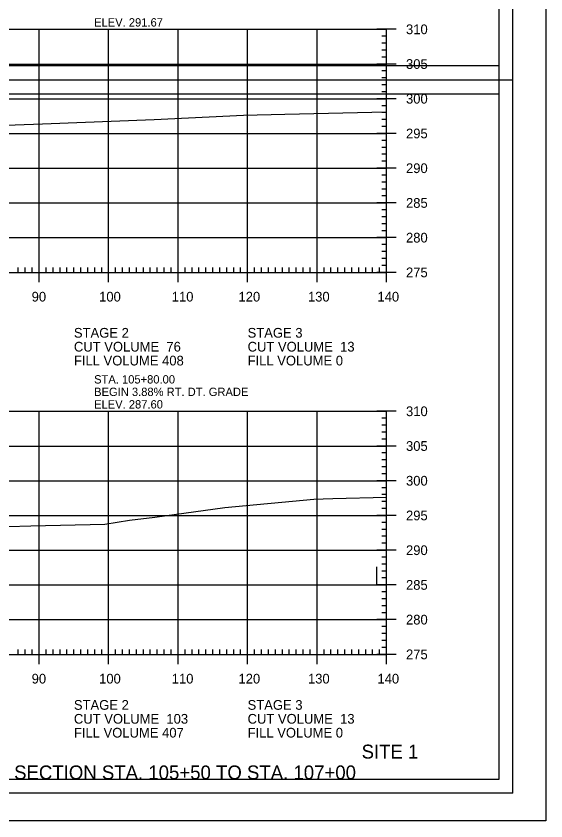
# Model space of a CAD drawing. Extents: x 1368713 to 1370673, y 380279 to 380950.
# Drawn here: x 1370239 to 1370315.2, y 380523.8 to 380639.7 of the extents above; entities that cross this region are included whole.
import ezdxf

# ---------------------------------------------------------------- set-up
doc = ezdxf.new("R2010")
doc.units = 0
for name, color, linetype in [('Notes', 7, 'Continuous'), ('R_Axis', 7, 'Continuous'), ('R_Axis Annot', 7, 'Continuous'), ('R_Border', 7, 'Continuous'), ('R_Border Plan-Plan', 7, 'Continuous'), ('R_Draft', 7, 'Continuous'), ('R_Exist Surface', 7, 'Continuous'), ('R_Grid', 7, 'Continuous'), ('R_No Plot', 7, 'Continuous'), ('R_Water', 7, 'Continuous')]:
    doc.layers.add(name, color=color, linetype=linetype)

msp = doc.modelspace()

# ---------------------------------------------------------------- linework, layer by layer
at = {"layer": 'R_Axis'}
for p, q in [((1370293.68, 380637.75), (1370290.88, 380637.75)), ((1370292.28, 380602.75), (1370292.28, 380637.75)), ((1370292.28, 380636.75), (1370291.58, 380636.75)), ((1370292.28, 380635.75), (1370291.58, 380635.75)), ((1370292.28, 380634.75), (1370291.58, 380634.75)), ((1370292.28, 380633.75), (1370291.58, 380633.75)), ((1370293.68, 380632.75), (1370290.88, 380632.75)), ((1370292.28, 380631.75), (1370291.58, 380631.75)), ((1370292.28, 380630.75), (1370291.58, 380630.75)), ((1370292.28, 380629.75), (1370291.58, 380629.75)), ((1370292.28, 380628.75), (1370291.58, 380628.75)), ((1370293.68, 380627.75), (1370290.88, 380627.75)), ((1370292.28, 380626.75), (1370291.58, 380626.75)), ((1370292.28, 380625.75), (1370291.58, 380625.75)), ((1370292.28, 380624.75), (1370291.58, 380624.75)), ((1370292.28, 380623.75), (1370291.58, 380623.75)), ((1370293.68, 380622.75), (1370290.88, 380622.75)), ((1370292.28, 380621.75), (1370291.58, 380621.75)), ((1370292.28, 380620.75), (1370291.58, 380620.75)), ((1370292.28, 380619.75), (1370291.58, 380619.75)), ((1370292.28, 380618.75), (1370291.58, 380618.75)), ((1370293.68, 380617.75), (1370290.88, 380617.75)), ((1370292.28, 380616.75), (1370291.58, 380616.75)), ((1370292.28, 380615.75), (1370291.58, 380615.75)), ((1370292.28, 380614.75), (1370291.58, 380614.75)), ((1370292.28, 380613.75), (1370291.58, 380613.75)), ((1370293.68, 380612.75), (1370290.88, 380612.75)), ((1370292.28, 380611.75), (1370291.58, 380611.75)), ((1370292.28, 380610.75), (1370291.58, 380610.75)), ((1370292.28, 380609.75), (1370291.58, 380609.75)), ((1370292.28, 380608.75), (1370291.58, 380608.75)), ((1370293.68, 380607.75), (1370290.88, 380607.75)), ((1370292.28, 380606.75), (1370291.58, 380606.75)), ((1370292.28, 380605.75), (1370291.58, 380605.75)), ((1370242.28, 380601.35), (1370242.28, 380604.15)), ((1370252.28, 380601.35), (1370252.28, 380604.15)), ((1370262.28, 380601.35), (1370262.28, 380604.15)), ((1370272.28, 380601.35), (1370272.28, 380604.15)), ((1370282.28, 380601.35), (1370282.28, 380604.15)), ((1370292.28, 380604.75), (1370291.58, 380604.75)), ((1370292.28, 380601.35), (1370292.28, 380604.15)), ((1370239.28, 380602.75), (1370239.28, 380603.45)), ((1370240.28, 380602.75), (1370240.28, 380603.45)), ((1370241.28, 380602.75), (1370241.28, 380603.45)), ((1370243.28, 380602.75), (1370243.28, 380603.45)), ((1370244.28, 380602.75), (1370244.28, 380603.45)), ((1370245.28, 380602.75), (1370245.28, 380603.45)), ((1370246.28, 380602.75), (1370246.28, 380603.45)), ((1370247.28, 380602.75), (1370247.28, 380603.45)), ((1370248.28, 380602.75), (1370248.28, 380603.45)), ((1370249.28, 380602.75), (1370249.28, 380603.45)), ((1370250.28, 380602.75), (1370250.28, 380603.45)), ((1370251.28, 380602.75), (1370251.28, 380603.45)), ((1370253.28, 380602.75), (1370253.28, 380603.45)), ((1370254.28, 380602.75), (1370254.28, 380603.45)), ((1370255.28, 380602.75), (1370255.28, 380603.45)), ((1370256.28, 380602.75), (1370256.28, 380603.45)), ((1370257.28, 380602.75), (1370257.28, 380603.45)), ((1370258.28, 380602.75), (1370258.28, 380603.45)), ((1370259.28, 380602.75), (1370259.28, 380603.45)), ((1370260.28, 380602.75), (1370260.28, 380603.45)), ((1370261.28, 380602.75), (1370261.28, 380603.45)), ((1370263.28, 380602.75), (1370263.28, 380603.45)), ((1370264.28, 380602.75), (1370264.28, 380603.45)), ((1370265.28, 380602.75), (1370265.28, 380603.45)), ((1370266.28, 380602.75), (1370266.28, 380603.45)), ((1370267.28, 380602.75), (1370267.28, 380603.45)), ((1370268.28, 380602.75), (1370268.28, 380603.45)), ((1370269.28, 380602.75), (1370269.28, 380603.45)), ((1370270.28, 380602.75), (1370270.28, 380603.45)), ((1370271.28, 380602.75), (1370271.28, 380603.45)), ((1370273.28, 380602.75), (1370273.28, 380603.45)), ((1370274.28, 380602.75), (1370274.28, 380603.45)), ((1370275.28, 380602.75), (1370275.28, 380603.45)), ((1370276.28, 380602.75), (1370276.28, 380603.45)), ((1370277.28, 380602.75), (1370277.28, 380603.45)), ((1370278.28, 380602.75), (1370278.28, 380603.45)), ((1370279.28, 380602.75), (1370279.28, 380603.45)), ((1370280.28, 380602.75), (1370280.28, 380603.45)), ((1370281.28, 380602.75), (1370281.28, 380603.45)), ((1370283.28, 380602.75), (1370283.28, 380603.45)), ((1370284.28, 380602.75), (1370284.28, 380603.45)), ((1370285.28, 380602.75), (1370285.28, 380603.45)), ((1370286.28, 380602.75), (1370286.28, 380603.45)), ((1370287.28, 380602.75), (1370287.28, 380603.45)), ((1370288.28, 380602.75), (1370288.28, 380603.45)), ((1370289.28, 380602.75), (1370289.28, 380603.45)), ((1370290.28, 380602.75), (1370290.28, 380603.45)), ((1370291.28, 380602.75), (1370291.28, 380603.45)), ((1370292.28, 380603.75), (1370291.58, 380603.75)), ((1370012.28, 380602.75), (1370292.28, 380602.75)), ((1370293.68, 380602.75), (1370290.88, 380602.75)), ((1370293.68, 380582.75), (1370290.88, 380582.75)), ((1370292.28, 380547.75), (1370292.28, 380582.75)), ((1370292.28, 380581.75), (1370291.58, 380581.75)), ((1370292.28, 380580.75), (1370291.58, 380580.75)), ((1370292.28, 380579.75), (1370291.58, 380579.75)), ((1370292.28, 380578.75), (1370291.58, 380578.75)), ((1370293.68, 380577.75), (1370290.88, 380577.75)), ((1370292.28, 380576.75), (1370291.58, 380576.75)), ((1370292.28, 380575.75), (1370291.58, 380575.75)), ((1370292.28, 380574.75), (1370291.58, 380574.75)), ((1370293.68, 380572.75), (1370290.88, 380572.75)), ((1370292.28, 380573.75), (1370291.58, 380573.75)), ((1370292.28, 380571.75), (1370291.58, 380571.75)), ((1370292.28, 380570.75), (1370291.58, 380570.75)), ((1370292.28, 380569.75), (1370291.58, 380569.75)), ((1370292.28, 380568.75), (1370291.58, 380568.75)), ((1370293.68, 380567.75), (1370290.88, 380567.75)), ((1370292.28, 380566.75), (1370291.58, 380566.75)), ((1370292.28, 380565.75), (1370291.58, 380565.75)), ((1370292.28, 380564.75), (1370291.58, 380564.75)), ((1370292.28, 380563.75), (1370291.58, 380563.75)), ((1370293.68, 380562.75), (1370290.88, 380562.75)), ((1370292.28, 380561.75), (1370291.58, 380561.75)), ((1370292.28, 380560.75), (1370291.58, 380560.75)), ((1370292.28, 380559.75), (1370291.58, 380559.75)), ((1370293.68, 380557.75), (1370290.88, 380557.75)), ((1370292.28, 380558.75), (1370291.58, 380558.75)), ((1370292.28, 380556.75), (1370291.58, 380556.75)), ((1370292.28, 380555.75), (1370291.58, 380555.75)), ((1370292.28, 380554.75), (1370291.58, 380554.75)), ((1370292.28, 380553.75), (1370291.58, 380553.75)), ((1370293.68, 380552.75), (1370290.88, 380552.75)), ((1370292.28, 380551.75), (1370291.58, 380551.75)), ((1370292.28, 380550.75), (1370291.58, 380550.75)), ((1370292.28, 380549.75), (1370291.58, 380549.75)), ((1370239.28, 380547.75), (1370239.28, 380548.45)), ((1370240.28, 380547.75), (1370240.28, 380548.45)), ((1370241.28, 380547.75), (1370241.28, 380548.45)), ((1370242.28, 380546.35), (1370242.28, 380549.15)), ((1370243.28, 380547.75), (1370243.28, 380548.45)), ((1370244.28, 380547.75), (1370244.28, 380548.45)), ((1370245.28, 380547.75), (1370245.28, 380548.45)), ((1370246.28, 380547.75), (1370246.28, 380548.45)), ((1370247.28, 380547.75), (1370247.28, 380548.45)), ((1370248.28, 380547.75), (1370248.28, 380548.45)), ((1370249.28, 380547.75), (1370249.28, 380548.45)), ((1370250.28, 380547.75), (1370250.28, 380548.45)), ((1370251.28, 380547.75), (1370251.28, 380548.45)), ((1370252.28, 380546.35), (1370252.28, 380549.15)), ((1370253.28, 380547.75), (1370253.28, 380548.45)), ((1370254.28, 380547.75), (1370254.28, 380548.45)), ((1370255.28, 380547.75), (1370255.28, 380548.45)), ((1370256.28, 380547.75), (1370256.28, 380548.45)), ((1370257.28, 380547.75), (1370257.28, 380548.45)), ((1370258.28, 380547.75), (1370258.28, 380548.45)), ((1370259.28, 380547.75), (1370259.28, 380548.45)), ((1370260.28, 380547.75), (1370260.28, 380548.45)), ((1370261.28, 380547.75), (1370261.28, 380548.45)), ((1370262.28, 380546.35), (1370262.28, 380549.15)), ((1370263.28, 380547.75), (1370263.28, 380548.45)), ((1370264.28, 380547.75), (1370264.28, 380548.45)), ((1370265.28, 380547.75), (1370265.28, 380548.45)), ((1370266.28, 380547.75), (1370266.28, 380548.45)), ((1370267.28, 380547.75), (1370267.28, 380548.45)), ((1370268.28, 380547.75), (1370268.28, 380548.45)), ((1370269.28, 380547.75), (1370269.28, 380548.45)), ((1370270.28, 380547.75), (1370270.28, 380548.45)), ((1370271.28, 380547.75), (1370271.28, 380548.45)), ((1370272.28, 380546.35), (1370272.28, 380549.15)), ((1370273.28, 380547.75), (1370273.28, 380548.45)), ((1370274.28, 380547.75), (1370274.28, 380548.45)), ((1370275.28, 380547.75), (1370275.28, 380548.45)), ((1370276.28, 380547.75), (1370276.28, 380548.45)), ((1370277.28, 380547.75), (1370277.28, 380548.45)), ((1370278.28, 380547.75), (1370278.28, 380548.45)), ((1370279.28, 380547.75), (1370279.28, 380548.45)), ((1370280.28, 380547.75), (1370280.28, 380548.45)), ((1370281.28, 380547.75), (1370281.28, 380548.45)), ((1370282.28, 380546.35), (1370282.28, 380549.15)), ((1370283.28, 380547.75), (1370283.28, 380548.45)), ((1370284.28, 380547.75), (1370284.28, 380548.45)), ((1370285.28, 380547.75), (1370285.28, 380548.45)), ((1370286.28, 380547.75), (1370286.28, 380548.45)), ((1370287.28, 380547.75), (1370287.28, 380548.45)), ((1370288.28, 380547.75), (1370288.28, 380548.45)), ((1370289.28, 380547.75), (1370289.28, 380548.45)), ((1370290.28, 380547.75), (1370290.28, 380548.45)), ((1370291.28, 380547.75), (1370291.28, 380548.45)), ((1370292.28, 380548.75), (1370291.58, 380548.75)), ((1370292.28, 380546.35), (1370292.28, 380549.15)), ((1370012.28, 380547.75), (1370292.28, 380547.75)), ((1370293.68, 380547.75), (1370290.88, 380547.75))]:
    msp.add_line(p, q, dxfattribs=at)
at = {"layer": 'R_Border'}
for q in [(1370310.46, 380733.21), (1369994.28, 380527.75)]:
    msp.add_line((1370310.46, 380527.75), q, dxfattribs=at)
at = {"layer": 'R_Border Plan-Plan'}
msp.add_line((1369994.28, 380630.48), (1370310.46, 380630.48), dxfattribs=at)
at = {"layer": 'R_Exist Surface'}
for points in [[(1370225.6, 380623.5), (1370242.76, 380624.13), (1370258.83, 380624.77), (1370271.67, 380625.4), (1370277.62, 380625.51), (1370292.28, 380625.89)], [(1370234.6, 380566.06), (1370241.06, 380566.25), (1370251.75, 380566.51), (1370255.26, 380567.08), (1370258.95, 380567.5), (1370269.02, 380568.9), (1370281.83, 380570.12), (1370283.17, 380570.16), (1370284.53, 380570.18), (1370292.28, 380570.37)]]:
    msp.add_lwpolyline(points, dxfattribs=at)
at = {"layer": 'R_Grid'}
for p, q in [((1370012.28, 380637.75), (1370292.28, 380637.75)), ((1370242.28, 380602.75), (1370242.28, 380637.75)), ((1370252.28, 380602.75), (1370252.28, 380637.75)), ((1370262.28, 380602.75), (1370262.28, 380637.75)), ((1370272.28, 380602.75), (1370272.28, 380637.75)), ((1370282.28, 380602.75), (1370282.28, 380637.75)), ((1370292.28, 380602.75), (1370292.28, 380637.75)), ((1370012.28, 380632.75), (1370292.28, 380632.75)), ((1370012.28, 380627.75), (1370292.28, 380627.75)), ((1370012.28, 380622.75), (1370292.28, 380622.75)), ((1370012.28, 380617.75), (1370292.28, 380617.75)), ((1370012.28, 380612.75), (1370292.28, 380612.75)), ((1370012.28, 380607.75), (1370292.28, 380607.75)), ((1370012.28, 380602.75), (1370292.28, 380602.75)), ((1370012.28, 380582.75), (1370292.28, 380582.75)), ((1370242.28, 380547.75), (1370242.28, 380582.75)), ((1370252.28, 380547.75), (1370252.28, 380582.75)), ((1370262.28, 380547.75), (1370262.28, 380582.75)), ((1370272.28, 380547.75), (1370272.28, 380582.75)), ((1370282.28, 380547.75), (1370282.28, 380582.75)), ((1370292.28, 380547.75), (1370292.28, 380582.75)), ((1370012.28, 380577.75), (1370292.28, 380577.75)), ((1370012.28, 380572.75), (1370292.28, 380572.75)), ((1370012.28, 380567.75), (1370292.28, 380567.75)), ((1370012.28, 380562.75), (1370292.28, 380562.75)), ((1370012.28, 380557.75), (1370292.28, 380557.75)), ((1370012.28, 380552.75), (1370292.28, 380552.75)), ((1370012.28, 380547.75), (1370292.28, 380547.75))]:
    msp.add_line(p, q, dxfattribs=at)
at = {"layer": 'R_No Plot'}
for points in [[(1369981.88, 380737.11), (1370315.22, 380737.11), (1370315.22, 380523.77), (1369981.88, 380523.77)], [(1370308.46, 380632.48), (1369996.28, 380632.48), (1369996.28, 380731.21), (1370245.82, 380731.21), (1370245.82, 380721.33), (1370263.36, 380721.33), (1370287.46, 380721.33), (1370287.46, 380699), (1370308.46, 380699)], [(1369996.28, 380731.21), (1370245.82, 380731.21), (1370245.82, 380721.33), (1370263.36, 380721.33), (1370287.46, 380721.33), (1370287.46, 380699), (1370308.46, 380699), (1370308.46, 380529.75), (1369996.28, 380529.75)], [(1369996.28, 380628.48), (1370308.46, 380628.48), (1370308.46, 380529.75), (1369996.28, 380529.75)]]:
    msp.add_lwpolyline(points, close=True, dxfattribs=at)
at = {"layer": 'R_Water'}
msp.add_line((1370290.88, 380557.75), (1370290.88, 380560.35), dxfattribs=at)

# ---------------------------------------------------------------- texts
at = {"layer": 'Notes'}
for s, p in [('ELEV. 291.67', (1370250.19, 380638.15)), ('STA. 105+80.00', (1370250.19, 380586.75)), ('BEGIN 3.88% RT. DT. GRADE', (1370250.19, 380584.95)), ('ELEV. 287.60', (1370250.19, 380583.15))]:
    msp.add_text(s, height=1.2, dxfattribs=at).set_placement(p)
at = {"layer": 'R_Axis Annot'}
for s, p in [('310', (1370295.08, 380637.05)), ('305', (1370295.08, 380632.05)), ('300', (1370295.08, 380627.05)), ('295', (1370295.08, 380622.05)), ('290', (1370295.08, 380617.05)), ('285', (1370295.08, 380612.05)), ('280', (1370295.08, 380607.05)), ('275', (1370295.08, 380602.05)), ('90', (1370241.2, 380598.55)), ('100', (1370250.91, 380598.55)), ('110', (1370261.36, 380598.55)), ('120', (1370270.97, 380598.55)), ('130', (1370280.97, 380598.55)), ('140', (1370290.97, 380598.55)), ('STAGE 2', (1370247.28, 380593.35)), ('STAGE 3', (1370272.28, 380593.35)), ('CUT VOLUME  76', (1370247.28, 380591.35)), ('CUT VOLUME  13', (1370272.28, 380591.35)), ('FILL VOLUME 408', (1370247.28, 380589.35)), ('FILL VOLUME 0', (1370272.28, 380589.35)), ('310', (1370295.08, 380582.05)), ('305', (1370295.08, 380577.05)), ('300', (1370295.08, 380572.05)), ('295', (1370295.08, 380567.05)), ('290', (1370295.08, 380562.05)), ('285', (1370295.08, 380557.05)), ('280', (1370295.08, 380552.05)), ('275', (1370295.08, 380547.05)), ('90', (1370241.2, 380543.55)), ('100', (1370250.91, 380543.55)), ('110', (1370261.36, 380543.55)), ('120', (1370270.97, 380543.55)), ('130', (1370280.97, 380543.55)), ('140', (1370290.97, 380543.55)), ('STAGE 2', (1370247.28, 380539.77)), ('STAGE 3', (1370272.28, 380539.77)), ('CUT VOLUME  103', (1370247.28, 380537.77)), ('CUT VOLUME  13', (1370272.28, 380537.77)), ('FILL VOLUME 407', (1370247.28, 380535.77)), ('FILL VOLUME 0', (1370272.28, 380535.77))]:
    msp.add_text(s, height=1.4, dxfattribs=at).set_placement(p)
at = {"layer": 'R_Draft'}
for s, p in [('SITE 1', (1370288.69, 380532.75)), ('CROSS SECTION STA. 105+50 TO STA. 107+00', (1370228.42, 380529.75))]:
    msp.add_text(s, height=2, dxfattribs=at).set_placement(p)

doc.saveas('drawing.dxf')
